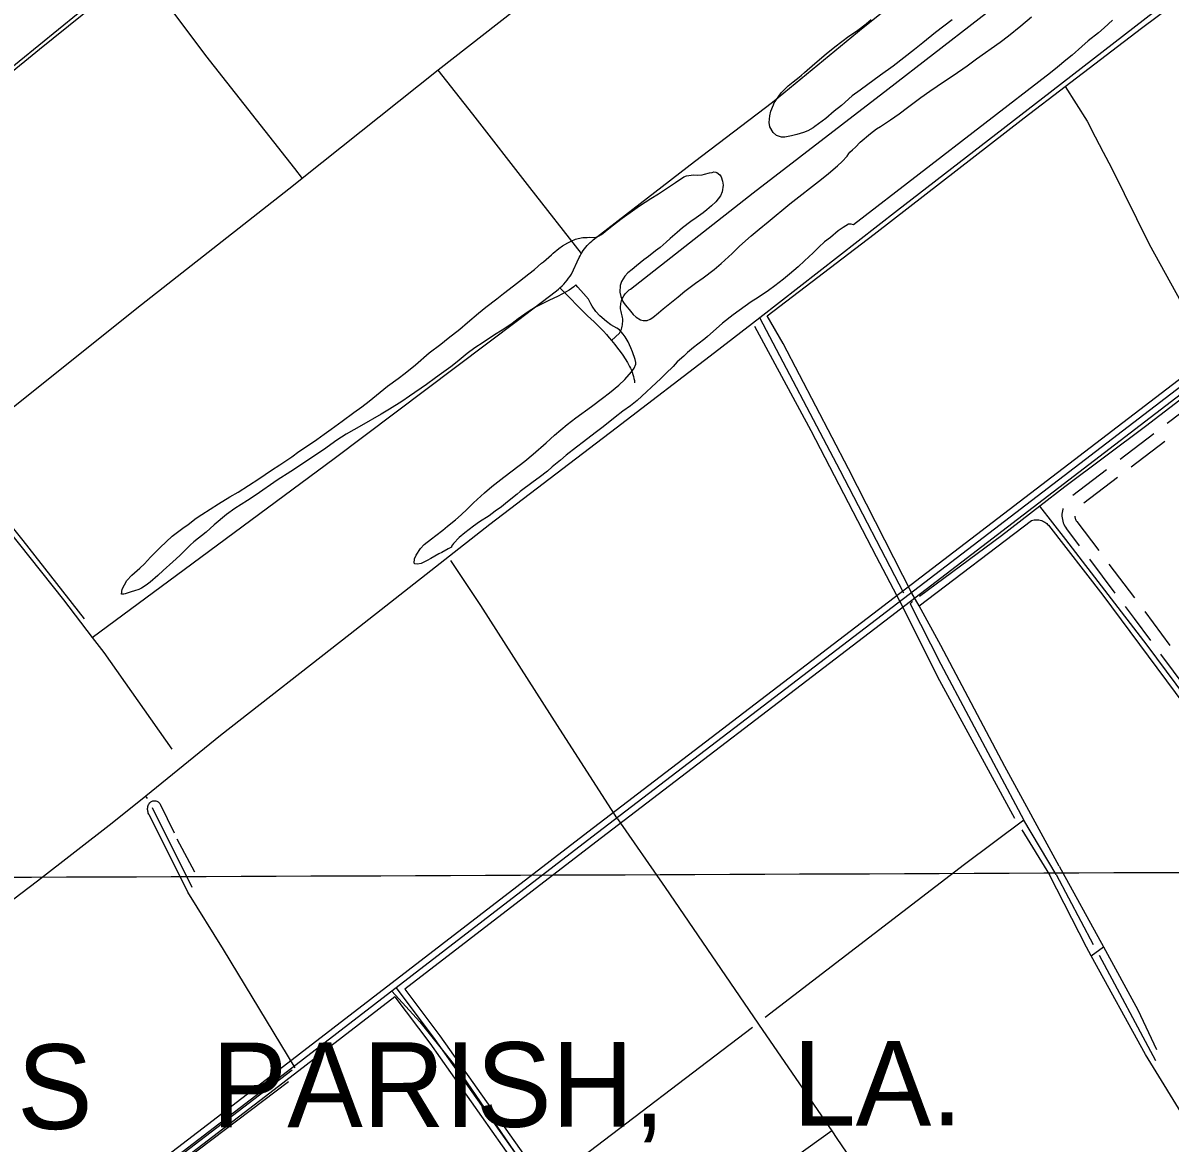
# Model space of a CAD drawing. Extents: x 3419139 to 3457078, y 540382 to 565875.
# Drawn here: x 3430044 to 3432751, y 557294 to 559939 of the extents above; entities that cross this region are included whole.
import ezdxf

# ---------------------------------------------------------------- set-up
doc = ezdxf.new("R2010")
doc.units = 0
for name, color, linetype in [('V-DTCH-CNTR', 7, 'Continuous'), ('V-GRID-MAJR', 7, 'Continuous'), ('V-ROAD-CNTR', 7, 'Continuous'), ('V-SITE-VEGE', 7, 'Continuous'), ('V-TOPO-GNAM-IDEN', 7, 'Continuous'), ('V-TOPO-SHOR', 7, 'Continuous')]:
    doc.layers.add(name, color=color, linetype=linetype)

msp = doc.modelspace()

# ---------------------------------------------------------------- linework, layer by layer
at = {"layer": 'V-DTCH-CNTR'}
for p, q in [((3432158.9, 558561.8), (3432424.6, 558763.8)), ((3431447.3, 558059), (3431559.9, 557896.8)), ((3432401.3, 558033.6), (3432466.4, 557927.4)), ((3430406.8, 558011.8), (3430448.2, 557934.2)), ((3432564.7, 557736.1), (3432593.9, 557756.7))]:
    msp.add_line(p, q, dxfattribs=at)
for points in [[(3429853.7, 559689.8), (3430082.4, 559877), (3430320.1, 560068.6), (3430369.1, 560108.1), (3430639.9, 560331.6), (3430956.7, 560585.1), (3431147.6, 560740.1), (3431173, 560760.7), (3431507.4, 561035.1), (3431758.3, 561244.8), (3432070.8, 561502.7), (3432217.6, 561622.8), (3432367.2, 561745.1), (3432625.3, 561955.8), (3432637.1, 561965.5), (3432783.2, 562093.1), (3432796.3, 562104.6), (3432946.9, 562228.1)], [(3431548.5, 560240), (3431349.1, 560082.2), (3431023.7, 559827), (3430702.9, 559571.5), (3430682.1, 559555), (3430312.2, 559264.6), (3429944.6, 558971)], [(3431800.5, 559247.1), (3432053, 559439.4), (3432407.2, 559714.2), (3432503.9, 559788.4), (3432683.7, 559926.2), (3432955.4, 560129.6)], [(3430320.1, 560068.6), (3430474.3, 559861.5), (3430684.6, 559594.9), (3430702.9, 559571.5)], [(3431432.9, 559188.7), (3431451.7, 559206.1), (3431453.4, 559209.2), (3431454.8, 559212.4), (3431456.1, 559215.7), (3431457.1, 559219), (3431458, 559222.4), (3431458.7, 559225.9), (3431459.1, 559229.3), (3431459.4, 559232.8), (3431459.4, 559236.3), (3431459.3, 559239.9), (3431458.9, 559243.3), (3431458.3, 559246.8), (3431457.6, 559250.2), (3431456.6, 559253.6), (3431455.4, 559256.9), (3431454.8, 559260.1), (3431454.4, 559263.2), (3431454.3, 559266.4), (3431454.3, 559269.7), (3431454.5, 559272.9), (3431454.9, 559276), (3431455.6, 559279.2), (3431456.4, 559282.3), (3431457.4, 559285.3), (3431458.7, 559288.3), (3431460.1, 559291.1), (3431461.7, 559293.9), (3431463.5, 559296.6), (3431465.4, 559299.1), (3431467.5, 559301.6), (3431469.7, 559303.9), (3431472.1, 559306), (3431474.6, 559308), (3431477.3, 559309.8), (3431767.1, 559537.3), (3432084.9, 559782.1), (3432408.3, 560033.4)], [(3430206.8, 558487.7), (3430424.4, 558647.9), (3430778, 558910.1), (3431210.9, 559235.7), (3431302.9, 559305.8), (3431307.5, 559309.6), (3431310.9, 559312.7), (3431316.2, 559317.7), (3431320.3, 559322), (3431324.2, 559326.4), (3431328, 559330.9), (3431331.6, 559335.6), (3431335.1, 559340.5), (3431338.4, 559345.4), (3431356.4, 559384.5), (3431358.6, 559388.9), (3431361, 559393.2), (3431361.7, 559394.3), (3431363.6, 559397.4), (3431366.3, 559401.5), (3431369.2, 559405.4), (3431372.3, 559409.2), (3431375.5, 559412.9), (3431378.9, 559416.4), (3431382.4, 559419.8), (3431386.1, 559423.1), (3431389.9, 559426.1), (3431628.9, 559611.6), (3431812.6, 559751.1), (3432026.5, 559927.5), (3432100.9, 559986.5)], [(3431361.7, 559394.3), (3431240.2, 559549.6), (3431105.3, 559722.9), (3431023.7, 559827)], [(3432503.9, 559788.4), (3432555.3, 559707), (3432574.2, 559670), (3432593.4, 559633.2), (3432612.9, 559596.6), (3432702.3, 559416.2), (3432777.6, 559279.5), (3432851.5, 559136.5)], [(3431310.9, 559312.7), (3431376.4, 559246.7), (3431384.1, 559239.8), (3431391.7, 559232.7), (3431399.2, 559225.5), (3431406.5, 559218.1), (3431413.7, 559210.6), (3431420.7, 559202.9), (3431427.5, 559195.1), (3431432.9, 559188.7), (3431440.7, 559179), (3431447, 559170.7), (3431453.2, 559162.4), (3431459.2, 559153.9), (3431465, 559145.3), (3431470.6, 559136.5), (3431473.2, 559132.1), (3431475.6, 559127.6), (3431477.8, 559123), (3431479.8, 559118.4), (3431481.6, 559113.6), (3431483.2, 559108.8), (3431484.6, 559103.9), (3431485.8, 559098.9), (3431486.8, 559093.9), (3431487.5, 559088.9)], [(3432489.4, 557947.4), (3432361.5, 558182.5), (3432210.5, 558468.6), (3432158.9, 558561.8), (3432142.1, 558592.2), (3431992, 558885.7), (3431838, 559181.3), (3431800.5, 559247.1)], [(3431770.3, 559222.5), (3431903.2, 558976.2), (3432057.9, 558678.7), (3432113.2, 558572.3)], [(3429894, 558856.2), (3429901.5, 558848.3), (3429909.2, 558840.6), (3429917.1, 558833.1), (3429925.2, 558825.8), (3429933.4, 558818.7), (3429941.8, 558811.7), (3429950.3, 558805), (3429958, 558798.2), (3429965.4, 558791.1), (3429972.7, 558783.9), (3429979.8, 558776.5), (3430139.1, 558576.3), (3430206.8, 558487.7), (3430234.3, 558451.8), (3430395, 558223.6)], [(3432424.6, 558763.8), (3432427.4, 558764.5), (3432430.3, 558765), (3432433.2, 558765.3), (3432436.1, 558765.4), (3432439, 558765.3), (3432441.8, 558764.9), (3432444.7, 558764.3), (3432447.5, 558763.5), (3432450.2, 558762.5), (3432452.9, 558761.3), (3432455.4, 558759.9), (3432457.8, 558758.2), (3432460.1, 558756.5), (3432462.3, 558754.5), (3432464.3, 558752.4), (3432593, 558587.5), (3432870.7, 558213.9), (3432969.5, 558089)], [(3431447.3, 558059), (3431311.1, 558271), (3431124.6, 558562.9), (3431053.9, 558669.1)], [(3432113.2, 558572.3), (3432207.3, 558385.9), (3432384, 558061.1)], [(3430398.3, 557956.2), (3430341.5, 558068.3), (3430340.4, 558070.4), (3430339.5, 558072.5), (3430338.8, 558074.7), (3430338.3, 558077), (3430338, 558079.2), (3430337.8, 558081.5), (3430337.9, 558083.9), (3430338.2, 558086.1), (3430338.7, 558088.4), (3430339.3, 558090.6), (3430340.2, 558092.8), (3430341.2, 558094.8), (3430342.4, 558096.8), (3430343.7, 558098.1), (3430345.2, 558099.2), (3430346.7, 558100.2), (3430348.4, 558100.9), (3430350.1, 558101.5), (3430351.9, 558101.8), (3430353.8, 558102), (3430355.6, 558101.9), (3430357.4, 558101.6), (3430359.2, 558101), (3430360.8, 558100.3), (3430362.4, 558099.4), (3430363.9, 558098.3), (3430365.2, 558097), (3430366.4, 558095.6), (3430367.3, 558094), (3430400.4, 558026.3)], [(3430685.8, 557471.6), (3430516.9, 557750.8), (3430432.4, 557885.7), (3430398.3, 557956.2)], [(3432489.4, 557947.4), (3432593.9, 557756.7), (3432675, 557608.6), (3432719.6, 557514.3)], [(3432796.4, 557335.2), (3432693.6, 557502.8), (3432564.7, 557736.1), (3432553.8, 557755.9), (3432466.4, 557927.4)], [(3431559.9, 557896.8), (3431790.2, 557559.2), (3431952.6, 557322.5), (3431964.7, 557304.8), (3432177.7, 556992), (3432216, 556934.9)], [(3430914.6, 557652.1), (3430980.3, 557580.1), (3431071.9, 557465.9), (3431244, 557213.9), (3431244.3, 557212.3), (3431280.7, 557163.9), (3431390.1, 557015.3), (3431437.9, 556950.1), (3431593.1, 556738.6), (3431807.3, 556441.9), (3431833.3, 556403.5), (3431849.4, 556378.6), (3431873.2, 556330.4)], [(3430678.9, 557466.1), (3430410.8, 557260.6), (3430348.4, 557212.7), (3430050.9, 556984.5), (3429713.3, 556725.7), (3429545.4, 556596.6), (3429339.7, 556438.4), (3429090.2, 556247.7), (3428991.5, 556172), (3428799.8, 556024.9), (3428589.7, 555861.6), (3428508.1, 555798.3), (3428179.2, 555545.7), (3428020.9, 555425.2), (3427990.4, 555402.1), (3427933.4, 555358.7), (3427874, 555313.3), (3427631.8, 555128.4), (3427476.3, 555006.9), (3427443.1, 554981.1), (3427144.3, 554749.3), (3427103.1, 554717.3)], [(3431952.6, 557322.5), (3431592.7, 557063.7), (3431454.9, 556962.2), (3431437.9, 556950.1)]]:
    msp.add_lwpolyline(points, dxfattribs=at)
at = {"layer": 'V-GRID-MAJR'}
msp.add_spline([(3423224.7, 557894.1), (3428498.4, 557915.2), (3433772.2, 557937), (3439045.9, 557959.6), (3444319.6, 557983), (3449593.3, 558007.2), (3454867, 558032.1)], degree=3, dxfattribs=at)
at = {"layer": 'V-ROAD-CNTR'}
for p, q in [((3432712.9, 558968.3), (3432633.4, 558907.7)), ((3432738.9, 558950.4), (3432659.4, 558889.8)), ((3432601.6, 558883.4), (3432522, 558822.8)), ((3432627.6, 558865.6), (3432548.1, 558804.9)), ((3432560.8, 558672.2), (3432621, 558592.4)), ((3432607.1, 558660.7), (3432667.3, 558580.8)), ((3432691.4, 558548.9), (3432751, 558468.6)), ((3432728.8, 558448.2), (3432788.4, 558367.9))]:
    msp.add_line(p, q, dxfattribs=at)
for points in [[(3433081.9, 559331.5), (3432807.5, 559122.4), (3432036.1, 558532), (3431377.3, 558027.9), (3430607.7, 557435.2), (3429763, 556788.4), (3429045.4, 556235.7), (3428369.2, 555717.5), (3427538.9, 555082.1), (3427196.1, 554815.3)], [(3433103.9, 559331.9), (3432816.6, 559110.5), (3432045.2, 558520), (3431386.4, 558016), (3430616.8, 557423.3), (3429772.2, 556776.5), (3429054.5, 556223.8), (3428378.3, 555705.6), (3427548, 555070.2), (3427205.3, 554803.5)], [(3433100.1, 559307.8), (3432825.7, 559098.6), (3432054.4, 558508.1), (3431395.6, 558004.1), (3430945.3, 557657.3)], [(3432824.7, 559052.6), (3432776.7, 559017), (3432744.7, 558992.6)], [(3432498.4, 558791.7), (3432498, 558790.3), (3432497.1, 558786.3), (3432496.5, 558782.3), (3432496.2, 558778.3), (3432496.2, 558774.3), (3432496.5, 558770.3), (3432497.1, 558766.3), (3432498, 558762.4), (3432499.2, 558758.5), (3432500.6, 558754.8), (3432502.3, 558751.1), (3432504.3, 558747.6), (3432506.5, 558744.3), (3432536.7, 558704.2)], [(3432526.3, 558774.2), (3432526.4, 558773.6), (3432526.6, 558771.8), (3432527, 558770), (3432527.6, 558768.2), (3432528.2, 558766.5), (3432529, 558764.8), (3432529.9, 558763.2), (3432531, 558761.6), (3432583, 558692.6)], [(3432645.1, 558560.5), (3432666.6, 558531.9), (3432704.9, 558480.3)], [(3430924.4, 557660.2), (3431015.8, 557538.3), (3431236.1, 557226.5), (3431300, 557143.9), (3431526.1, 556828.1)], [(3430945.3, 557657.3), (3431027.9, 557547.2), (3431248.1, 557235.5), (3431312.1, 557152.8), (3431538.3, 556836.8)], [(3430921.5, 557639), (3430626, 557411.4), (3429781.3, 556764.6), (3429063.6, 556211.9), (3428387.4, 555693.6), (3427557.2, 555058.3), (3427214.5, 554791.6)], [(3430921.5, 557639), (3431003.7, 557529.5), (3431223.9, 557217.8)]]:
    msp.add_lwpolyline(points, dxfattribs=at)
at = {"layer": 'V-SITE-VEGE'}
for points in [[(3432615.2, 559945.1), (3432596.1, 559927), (3432582.2, 559915), (3432558.4, 559896.3), (3432543.3, 559883.2), (3432520.2, 559862.7), (3432505.2, 559850.7), (3432485.8, 559834.1), (3432468.9, 559820.7), (3432003.7, 559462.2), (3431998.7, 559463.7), (3431992.5, 559463.5), (3431979.8, 559455.8), (3431968.1, 559447.3), (3431949.7, 559432.1), (3431935.5, 559421.6), (3431922.2, 559408.8), (3431908.7, 559396.1), (3431888.5, 559376.6), (3431873.8, 559362.8), (3431852.9, 559345.5), (3431838.9, 559333.5), (3431818.4, 559317.6), (3431803.5, 559307.1), (3431779, 559290.5), (3431762.2, 559279.7)], [(3432237, 559945.9), (3432217.2, 559931.1), (3432197.5, 559915.9), (3432168.1, 559891.5), (3432148.4, 559875.7), (3432097.5, 559836.5), (3432067.5, 559815.4), (3432019.9, 559779.5), (3432001.3, 559766.1), (3431975.6, 559743.8), (3431958.8, 559730.4), (3431938.6, 559713.1), (3431913, 559694.1), (3431908.6, 559690.6), (3431896.2, 559683.6), (3431886.4, 559679.8), (3431870.1, 559675), (3431857.7, 559671.6), (3431841.8, 559668.7), (3431833.9, 559668.8), (3431822, 559672.6), (3431814.6, 559680), (3431806.5, 559693.5), (3431804.9, 559703.3), (3431806.3, 559719.1), (3431809, 559730.3), (3431815.4, 559744.9), (3431816.9, 559749.6), (3431825.9, 559763.5), (3431833.6, 559773.5), (3431849.8, 559790.2), (3431861.9, 559799.7), (3431875.8, 559810.2), (3431881.3, 559815.6), (3431888.6, 559821.6), (3431912.5, 559842.8), (3431939.6, 559865.7), (3431959.7, 559882), (3431993.4, 559907.3), (3432010.9, 559919.3), (3432033.6, 559936.2), (3432046.1, 559946.4)], [(3432111.7, 559723.7), (3432131.8, 559738.5), (3432162.9, 559762.1), (3432184.5, 559777.6), (3432219.2, 559800.7), (3432239.7, 559814.8), (3432272.5, 559836.9), (3432294.5, 559853.5), (3432350.1, 559892.9), (3432370.2, 559908.4), (3432398.8, 559931.4), (3432424.4, 559952.9)], [(3431317.5, 559412.3), (3431329.9, 559419.6), (3431337.9, 559423.1), (3431347.7, 559427.6), (3431353.9, 559429.3), (3431365.1, 559432), (3431369.4, 559432.2), (3431375.6, 559432.1), (3431379.9, 559432.4), (3431389.6, 559432.2), (3431396.5, 559432.8), (3431404.1, 559435.6), (3431408.9, 559438.7), (3431418, 559445.8), (3431426.8, 559453.2), (3431444.4, 559467.7), (3431458.3, 559477.9), (3431482.1, 559495.2), (3431498.9, 559506.4), (3431525.6, 559524), (3431543.8, 559534.8), (3431583.6, 559561.9), (3431603.7, 559574.9), (3431609.9, 559577.3), (3431626.2, 559579.5), (3431635.2, 559579.3), (3431646.8, 559580.2), (3431652.6, 559581.5), (3431664.5, 559584.9), (3431670.7, 559585.5), (3431674.7, 559586.6), (3431679, 559586.5), (3431681.5, 559585.3), (3431688.3, 559579.5), (3431691.8, 559575.1), (3431695.2, 559565.3), (3431696.8, 559555.5), (3431694.4, 559539.6), (3431690.2, 559530.3), (3431679.2, 559516.5), (3431668.9, 559506.5), (3431658.2, 559497.4), (3431649.1, 559490.3), (3431632.6, 559478.3), (3431620.2, 559469.5), (3431600.4, 559454.7), (3431588, 559444.1), (3431571.5, 559429.6), (3431561.6, 559421.2), (3431547.6, 559408.4), (3431537, 559400.7), (3431520.2, 559387.3), (3431509.2, 559378.8), (3431491.6, 559365.1), (3431481.4, 559356.6), (3431471.5, 559348.1), (3431464.1, 559340.3), (3431456.7, 559328.2), (3431453.6, 559318.8), (3431452.6, 559303), (3431454.6, 559292.5), (3431459.8, 559280.5), (3431462.9, 559275.7), (3431469.3, 559268), (3431474.2, 559261.8), (3431483.8, 559250.4), (3431490.9, 559243.8), (3431500.9, 559237.5), (3431507.7, 559235.9), (3431517.4, 559236.1), (3431524, 559238.9), (3431530.5, 559243.1), (3431544.1, 559254.4), (3431554.7, 559263.6), (3431589.9, 559291.8), (3431606, 559304.9), (3431631.3, 559323.9), (3431649.2, 559336.9), (3431675.2, 559356.7), (3431691.7, 559370.8), (3431717.7, 559394.1), (3431735.3, 559411.1), (3431762.9, 559435.9), (3431781.6, 559451.8), (3431802.4, 559468.7), (3431853.7, 559511.1), (3431928.8, 559570), (3431945.3, 559583.4), (3431966.5, 559601.4), (3431977.5, 559611.3), (3431989, 559624.1), (3431993, 559630.2), (3431995.6, 559633.8), (3432001.9, 559639.1), (3432008.5, 559645.1), (3432019.9, 559657.1), (3432044.1, 559677.6), (3432058, 559688.6), (3432067.8, 559693.8), (3432091.6, 559709.6), (3432111.7, 559723.7)], [(3431343.8, 559315.4), (3431333.2, 559307.7), (3431306.6, 559293.4), (3431284.8, 559283.3), (3431253.5, 559267.6), (3431235.9, 559256.4), (3431212.6, 559240.2), (3431198.6, 559228.6), (3431174.9, 559212.8), (3431156.3, 559201.9), (3431129.6, 559183.6), (3431110.2, 559171), (3431092.3, 559158), (3431068.5, 559138.2), (3431053.9, 559126.6), (3431031.6, 559110.7), (3431017.6, 559100.2), (3430996.4, 559085), (3430956.2, 559056.9), (3430938, 559044.9), (3430909.1, 559026.7), (3430889, 559014.4), (3430842.7, 558988.2), (3430806.6, 558967.2), (3430784.4, 558953.6), (3430752.9, 558930.7), (3430675.8, 558879.4), (3430643.7, 558859), (3430594.4, 558824.6), (3430573.9, 558811.2), (3430543.6, 558791.9), (3430523.9, 558778.2), (3430495.3, 558753.5), (3430476.2, 558736.5), (3430446.9, 558713.6), (3430438.4, 558705.4), (3430413.5, 558681), (3430397.3, 558666.1), (3430374.9, 558646), (3430361.7, 558633.6), (3430344.1, 558618.4), (3430334.6, 558611), (3430323.3, 558604), (3430317.1, 558600.5), (3430306.9, 558597.4), (3430298.6, 558595), (3430285.1, 558590.6), (3430281.5, 558589.6), (3430276.1, 558590), (3430277.4, 558601.9), (3430289, 558621.9), (3430300.7, 558634.7), (3430319.1, 558651), (3430330.4, 558661.2), (3430344.4, 558676.8), (3430367.2, 558699.9), (3430395.5, 558726.4), (3430408, 558736.3), (3430420.8, 558745.8), (3430433.6, 558754.6), (3430452.2, 558769.1), (3430465.7, 558777.5), (3430505.5, 558802.7), (3430532.2, 558819.2), (3430551.9, 558830.8), (3430600.4, 558862), (3430630.1, 558882.4), (3430650.1, 558895), (3430677.9, 558914), (3430695.1, 558926.7), (3430720.3, 558943.5), (3430737.5, 558954.8), (3430754.7, 558967.5), (3430771.1, 558979.1), (3430797.4, 558998.1), (3430824.5, 559018.5), (3430843.5, 559031.9), (3430861.1, 559045.6), (3430904, 559080.6), (3430929.6, 559099.2), (3430946, 559111.9), (3430970.2, 559131.3), (3431002.8, 559159.2), (3431029.6, 559180.1), (3431047.1, 559194.2), (3431074.6, 559215.7), (3431092.6, 559231.2), (3431118.6, 559253.1), (3431136.2, 559267.6), (3431162.2, 559287), (3431177.9, 559299.3), (3431201.3, 559318), (3431216, 559328.9), (3431237.9, 559345.9), (3431251.1, 559356.5), (3431267.6, 559371), (3431272.4, 559374.8), (3431291.1, 559390.7), (3431295.5, 559394.6), (3431308.7, 559405.9), (3431317.5, 559412.3)], [(3431762.2, 559279.7), (3431720.1, 559249.4), (3431694.9, 559229.3), (3431680.2, 559216.5), (3431659.7, 559198.5), (3431653.4, 559192.9), (3431636.6, 559179.8), (3431626.7, 559172.4), (3431612.4, 559160), (3431603.6, 559151.5), (3431587.8, 559138.1), (3431578.2, 559127.5), (3431561.3, 559110.8), (3431549.6, 559098.8), (3431493.4, 559047.4), (3431477.3, 559034.4), (3431459.7, 559021.7), (3431441.1, 559007.3), (3431413.2, 558985), (3431394.6, 558970.6), (3431367.1, 558949.4), (3431349.9, 558936.7), (3431326.1, 558918.1), (3431312.6, 558906), (3431293.1, 558890.1), (3431281.8, 558880.2), (3431262.4, 558865.1), (3431248.1, 558854.9), (3431217.4, 558832), (3431210.1, 558826), (3431187.3, 558808), (3431173.1, 558796.3), (3431158.1, 558785.4), (3431143.8, 558774.9), (3431121.2, 558760.5), (3431107.3, 558750.6), (3431086.4, 558734.8), (3431073.6, 558723.8), (3431060, 558709.3), (3431055.5, 558703.2), (3431054.8, 558701.1), (3431047.5, 558696.5), (3431032.5, 558688.1), (3431024.9, 558684.6), (3431006.3, 558674.2), (3430997.5, 558668.9), (3430983.7, 558661.9), (3430975, 558660.6), (3430968.5, 558661.1), (3430967.4, 558662.9), (3430968, 558673), (3430971.8, 558681.6), (3430981.8, 558697.3), (3430990.6, 558706.9), (3431007.8, 558720.3), (3431018.1, 558728.1), (3431034.5, 558740.8), (3431045.9, 558750.3), (3431064.2, 558765.1), (3431077.8, 558777.1), (3431092.1, 558790.2), (3431107.2, 558805.1), (3431132.9, 558828.8), (3431150.5, 558843.7), (3431178.3, 558866.3), (3431198.1, 558881.1), (3431228.1, 558904), (3431248.2, 558920.6), (3431278.3, 558947.1), (3431298.1, 558965.1), (3431328.2, 558990.6), (3431348.3, 559006.1), (3431385.6, 559032.8), (3431411.2, 559052.2), (3431428.4, 559064.9), (3431450.4, 559083.6), (3431464.4, 559096.7), (3431479.8, 559114.8), (3431486.1, 559123.7), (3431489.9, 559133), (3431490, 559137), (3431488.7, 559143.9), (3431482.1, 559161.7), (3431478.4, 559171.5), (3431472.5, 559185.3), (3431465.1, 559197.7), (3431460.5, 559204), (3431452.1, 559213.5), (3431445.6, 559217.9), (3431431.3, 559225.8), (3431421.4, 559233.2), (3431405.4, 559246.8), (3431396.2, 559257.1), (3431387.4, 559269.5), (3431383.9, 559275.4), (3431380.8, 559281.9), (3431378.3, 559286.3), (3431367, 559299.5), (3431353.2, 559314.5), (3431348.3, 559320.4), (3431343.8, 559315.4)]]:
    msp.add_lwpolyline(points, dxfattribs=at)
at = {"layer": 'V-TOPO-SHOR'}
for p, q in [((3430337.2, 558107.5), (3430333.4, 558112.9)), ((3430442.6, 557897), (3430349.3, 558085)), ((3432405.9, 558056.4), (3432266.4, 557951.4)), ((3432482.3, 557927.6), (3432405.9, 558056.4)), ((3432266.4, 557951.4), (3431795.6, 557589.8)), ((3432482.3, 557927.6), (3432569.9, 557762.8)), ((3432584, 557737.7), (3432717, 557488.3)), ((3431765.8, 557566.3), (3431279.4, 557196.9)), ((3430670.1, 557438.3), (3430365.1, 557207.5))]:
    msp.add_line(p, q, dxfattribs=at)
for points in [[(3431133.2, 560741.5), (3430942.1, 560589), (3430708.6, 560401.1), (3430436.7, 560178), (3430266.9, 560037.2), (3430034.6, 559847.7), (3429856.1, 559701.6)], [(3432909, 560112.8), (3432736.6, 559982.2), (3432450.7, 559761.3), (3432107.8, 559495.4), (3431783, 559242.5), (3431676, 559159.4), (3431443.5, 558981.6), (3431145.3, 558754.2), (3430815.8, 558495.5), (3430510.1, 558255.8), (3430333.4, 558112.9), (3430254, 558048.8), (3430078.1, 557912.4)], [(3432123.1, 558591.8), (3431972.8, 558881.9), (3431783, 559242.5)], [(3432957.2, 559187.6), (3432693.4, 558985.8), (3432502.9, 558843), (3432443.7, 558797.2), (3432353.8, 558727.6), (3432160.2, 558584.5)], [(3430188.7, 558531.3), (3430044, 558716.8), (3429944.5, 558839.9), (3429932.6, 558851)], [(3432799, 558350.1), (3432793.5, 558345.2), (3432788.4, 558346.8), (3432697.5, 558469), (3432505.1, 558718.5), (3432443.7, 558797.2)], [(3432143.6, 558572.4), (3432137.6, 558567), (3432209.9, 558424.2), (3432405.9, 558056.4)], [(3430078.1, 557912.4), (3429495.9, 557469.5), (3429136.6, 557189.3), (3428758.5, 556890.3), (3428418, 556632), (3428021, 556322.1), (3427710.3, 556081), (3427434.2, 555866.6), (3427426.3, 555855.6), (3427429.4, 555847.8), (3427434.1, 555841.5), (3427542.1, 555698.7), (3427828.6, 555325.3), (3427828.6, 555312.7), (3427472.4, 555041.9), (3427133.5, 554779)]]:
    msp.add_lwpolyline(points, dxfattribs=at)

# ---------------------------------------------------------------- texts
at = {"layer": 'V-TOPO-GNAM-IDEN'}
for s, p in [('PARISH,', (3430489.1, 557330.7)), ('LA.', (3431860.5, 557334.6)), ('JAMES', (3429316.5, 557325.6))]:
    msp.add_text(s, height=200, rotation=0.088, dxfattribs=at).set_placement(p)

doc.saveas('drawing.dxf')
